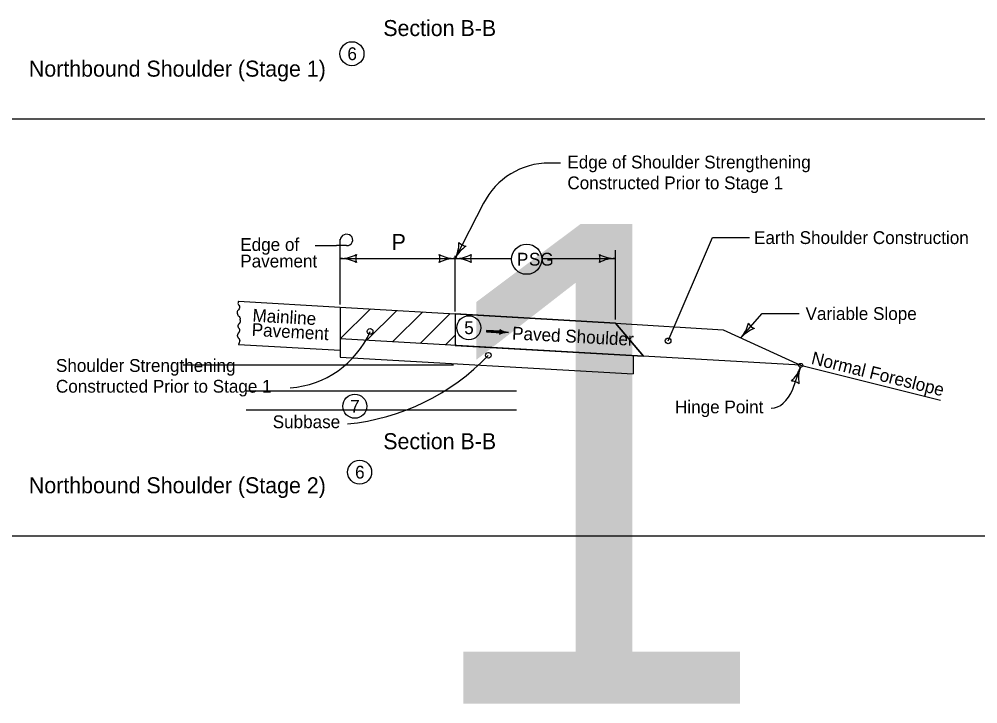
# Model space of a CAD drawing. Extents: x 10133 to 81668, y 7924 to 12229.
# Drawn here: x 11002 to 12201, y 10409 to 11265 of the extents above; entities that cross this region are included whole.
import ezdxf

# ---------------------------------------------------------------- set-up
doc = ezdxf.new("R2010")
doc.units = 0
for name, color, linetype in [('Cell', 7, 'Continuous'), ('dsnTextFinalPlan', 7, 'Continuous'), ('Level 1', 7, 'Continuous'), ('Level 12', 7, 'Continuous'), ('Level 4', 7, 'Continuous'), ('SheetText', 7, 'Continuous')]:
    doc.layers.add(name, color=color, linetype=linetype)

msp = doc.modelspace()

# ---------------------------------------------------------------- linework, layer by layer
at = {"layer": 'Cell'}
for p, q in [((11747.9, 10885.3), (11547.4, 10896.9)), ((11547.4, 10896.9), (11547.4, 10857.1)), ((11783, 10843.8), (11747.9, 10885.3)), ((11547.4, 10857.1), (11783, 10843.8))]:
    msp.add_line(p, q, dxfattribs=at)
at = {"layer": 'dsnTextFinalPlan'}
for p, q in [((11276.2, 10912.7), (11403.6, 10905.3)), ((11403.6, 10905.3), (11403.6, 10851.3)), ((11403.6, 10905.3), (11747.9, 10885.2)), ((11547.4, 10896.9), (11547.4, 10857.1)), ((11747.5, 10885.4), (11747.5, 10885.4)), ((11747.9, 10885.3), (11882.7, 10876.9)), ((11747.9, 10885.2), (11783, 10843.8)), ((11882.7, 10876.9), (11979.7, 10832.5)), ((11276.2, 10858.7), (11403.6, 10851.3)), ((11979.7, 10832.5), (11403.6, 10865.7)), ((11770.2, 10858.9), (11770.2, 10858.9)), ((11403.6, 10851.3), (11403.6, 10842.8)), ((11403.6, 10842.8), (11770.2, 10821.7)), ((11770.2, 10844.5), (11770.2, 10821.7)), ((11206.9, 10833.3), (11545.4, 10833.3)), ((11979.7, 10832.5), (12154.7, 10789.1)), ((11285.6, 10800.4), (11624.1, 10800.4)), ((11285.6, 10776.7), (11624.1, 10776.7))]:
    msp.add_line(p, q, dxfattribs=at)
msp.add_ellipse((11979.7, 10832.5), major_axis=(2.58, 0), ratio=0.913811, dxfattribs=at)
for points in [[(11276.2, 10912.7), (11275.7, 10909.1), (11276.7, 10907.6), (11277.6, 10905.3), (11277, 10903.2), (11275.1, 10900.8), (11274.5, 10898.9), (11275.1, 10896.6), (11275.9, 10894.3), (11277, 10893.6), (11278.3, 10891), (11278.3, 10890.2)], [(11276.4, 10873.1), (11276.6, 10873.3), (11276.8, 10873.6), (11277.1, 10874.1), (11277.4, 10874.7), (11277.5, 10875), (11277.6, 10875.4), (11277.8, 10876), (11277.8, 10876.6), (11277.8, 10877.2), (11277.7, 10877.5), (11277.7, 10877.6), (11277.6, 10877.7), (11277.4, 10878.1), (11277.1, 10878.5), (11276.8, 10878.8), (11276.6, 10879.2), (11276.4, 10879.5), (11276.3, 10879.8), (11276, 10880.4), (11275.8, 10880.9), (11275.8, 10881.2), (11275.7, 10881.5), (11275.7, 10881.6), (11275.7, 10881.8), (11275.9, 10882.6), (11276.1, 10883.1), (11276.3, 10883.6), (11276.8, 10884.2), (11277.3, 10884.8), (11277.8, 10885.3), (11278, 10885.6), (11278.2, 10886), (11278.4, 10886.4), (11278.6, 10886.9), (11278.7, 10887.4), (11278.7, 10887.6), (11278.7, 10887.7), (11278.8, 10887.9), (11278.7, 10888.4), (11278.6, 10888.9), (11278.5, 10889), (11278.4, 10889.1), (11278.4, 10889.3), (11278.4, 10889.4), (11278.3, 10890.2)], [(11276.4, 10873.1), (11276.2, 10872.8), (11275.9, 10872.6), (11275.7, 10872.4), (11275.5, 10872.1), (11275.4, 10871.8), (11275.2, 10871.5), (11275, 10870.9), (11274.8, 10870.7), (11274.8, 10870.4), (11274.7, 10870.1), (11274.7, 10869.9), (11274.6, 10869.8), (11274.6, 10869.3), (11274.8, 10868.8), (11275, 10868.2), (11275.2, 10867.7), (11275.7, 10867.1), (11276.2, 10866.6), (11276.7, 10866), (11276.9, 10865.7), (11277.1, 10865.4), (11277.5, 10864.4), (11277.7, 10863.9), (11277.7, 10863.5), (11277.6, 10863.2), (11277.6, 10862.9), (11277.5, 10862.6), (11277.5, 10862.3), (11277.1, 10861.2), (11277, 10860.6), (11276.8, 10860), (11276.5, 10859.4), (11276.4, 10859.1), (11276.3, 10858.8), (11276.2, 10858.7)]]:
    msp.add_spline(points, degree=3, dxfattribs=at)
at = {"layer": 'Level 1'}
msp.add_line((10147.1, 10619.2), (13242.8, 10619.2), dxfattribs=at)
at = {"layer": 'Level 12'}
for centre in [(11418.2, 11222.2), (11564.4, 10879.5), (11421.7, 10781.3), (11427.8, 10698.9)]:
    msp.add_circle(centre, 15, dxfattribs=at)
at = {"layer": 'Level 4'}
msp.add_line((12302.7, 11140.2), (10147.1, 11140.2), dxfattribs=at)
for centre in [(11440.9, 10874.9), (11440.9, 10874.9), (11813.9, 10863.1), (11813.9, 10863.1), (11588.9, 10845), (11588.9, 10845)]:
    msp.add_circle(centre, 3.54, dxfattribs=at)
at = {"layer": 'SheetText'}
for p, q in [((11665.1, 11085.6), (11679.4, 11085.6)), ((11582.7, 11035.2), (11547.4, 10966)), ((11403.6, 10969.3), (11403.6, 10990.2)), ((11813.9, 10863.1), (11869.6, 10992.2)), ((11869.6, 10992.2), (11915.9, 10992.2)), ((11372.3, 10982.2), (11398.9, 10982.2)), ((11411.4, 10982.2), (11398.9, 10982.2)), ((11403.6, 10908.4), (11403.6, 10969.3)), ((11547.4, 10899.8), (11547.4, 10969.3)), ((11655.8, 10966.2), (11747.9, 10966.2)), ((11747.9, 10889.9), (11747.9, 10976.5)), ((11403.6, 10966), (11618, 10966)), ((11403.6, 10865.7), (11441.4, 10903.1)), ((11436.7, 10863.8), (11474.5, 10901.2)), ((11468.9, 10861.9), (11506.7, 10899.3)), ((11503.5, 10859.9), (11541.3, 10897.3)), ((11904.9, 10866.8), (11931.5, 10897.2)), ((11931.5, 10897.2), (11977.8, 10897.2)), ((11535.1, 10858.1), (11547.4, 10870.2)), ((11604.7, 10874.2), (11586.5, 10875.2)), ((11604.6, 10873.2), (11604.6, 10873.2)), ((11604.7, 10875.2), (11604.7, 10875.2)), ((11970, 10802.5), (11979.4, 10830.1))]:
    msp.add_line(p, q, dxfattribs=at)
for points in [[(11604.7, 10875.1), (11586.5, 10876.2), (11586.4, 10874.3), (11604.6, 10873.2), (11604.6, 10874.8), (11586.7, 10875.9), (11586.7, 10874.4), (11604.2, 10873.5), (11604.3, 10874.6), (11587, 10875.7), (11586.9, 10874.7), (11604, 10873.7), (11604.1, 10874.4), (11587.2, 10875.4), (11587.1, 10874.9), (11603.7, 10873.9)], [(11604.3, 10876.4), (11605, 10875.2), (11605, 10873.5), (11604.2, 10872.1), (11606.9, 10873), (11610.1, 10873.7), (11611, 10873.8), (11608.8, 10874.3), (11605.6, 10875.6), (11604.6, 10876.1), (11604.7, 10872.6), (11609.7, 10873.8), (11605.1, 10875.4), (11605.1, 10873), (11608.5, 10873.9), (11605.5, 10874.8), (11605.2, 10873.4), (11607.4, 10873.9), (11605.8, 10874.4), (11605.7, 10873.7), (11606.5, 10873.9)]]:
    msp.add_lwpolyline(points, dxfattribs=at)
msp.add_circle((11636.9, 10965.2), 18.9, dxfattribs=at)
for centre, radius, start, end in [((11665.1, 10993.1), 92.4, 90, 152.9341), ((11509.5, 10985.3), 42.5, 332.9341, 1.0066), ((11585.2, 10946.7), 42.5, 124.8616, 152.9341), ((11563.6, 10997.7), 16.4, 225.2008, 260.6675), ((11403.6, 11008.5), 42.5, 270, 298.0725), ((11439.3, 10966), 16.4, 162.2666, 197.7334), ((11511.8, 10966), 16.4, 342.2666, 17.7334), ((11547.4, 11008.5), 42.5, 241.9275, 270), ((11547.4, 11008.5), 42.5, 270, 298.0725), ((11583, 10966), 16.4, 162.2666, 197.7334), ((11712.3, 10966.2), 16.4, 342.2666, 17.7333), ((11747.9, 11008.7), 42.5, 241.9275, 270), ((11747.9, 10923.7), 42.5, 90, 118.0725), ((11403.6, 10923.5), 42.5, 61.9275, 90), ((11547.4, 10923.5), 42.5, 90, 118.0725), ((11547.4, 10923.5), 42.5, 61.9275, 90), ((11872.9, 10894.7), 42.5, 318.8454, 346.9178), ((11928.3, 10893.6), 16.4, 211.112, 246.5787), ((11332.4, 10923), 118.9, 274.0851, 336.0699), ((11936.9, 10838.8), 42.5, 110.7729, 138.8454), ((11384.9, 11039.8), 282, 275.6784, 316.2844), ((11939.2, 10843.9), 42.5, 312.9788, 341.0513), ((12019.6, 10816.3), 42.5, 161.0513, 189.1238), ((11967.9, 10796.4), 16.4, 53.3179, 88.7846)]:
    msp.add_arc(centre, radius, start, end, dxfattribs=at)
for centre, major_axis, ratio, start_param, end_param in [((11411.4, 10989.3), (-7.81, 0), 0.913811, 1.570796, 6.283185), ((11600.9, 10874.4), (3.88, 0), 0.913811, 5.202895, 7.237436), ((11613.2, 10853.4), (22.2, 0), 0.913811, 1.537172, 2.061295), ((11615.9, 10893.8), (-22.2, 0), 0.913811, 0.954258, 1.478381), ((11942.9, 10840.4), (0, 61.5), 0.559383, 3.141593, 4.048985)]:
    msp.add_ellipse(centre, major_axis=major_axis, ratio=ratio, start_param=start_param, end_param=end_param, dxfattribs=at)

# ---------------------------------------------------------------- texts
at = {"layer": 'Level 12'}
for s, p in [('6', (11412.5, 11214.2)), ('5', (11558.7, 10871.5)), ('7', (11416, 10773.3)), ('6', (11422.1, 10690.9))]:
    msp.add_text(s, height=16, dxfattribs=at).set_placement(p)
at = {"layer": 'SheetText'}
for s, height, p in [('Section B-B', 20, (11457.4, 11244.3)), ('Northbound Shoulder (Stage 1)', 20, (11013.8, 11193.5)), ('Edge of Shoulder Strengthening', 16, (11687.8, 11078.7)), ('Constructed Prior to Stage 1', 16, (11687.8, 11052.7)), ('1', 600, (11496.6, 10409.2)), ('Edge of ', 16, (11278.4, 10975.6)), ('P', 20, (11467.8, 10976.7)), ('Earth Shoulder Construction', 16, (11921.4, 10984.2)), ('Pavement', 16, (11278.4, 10954.9)), ('P', 16, (11624.7, 10957.2)), ('SG', 16, (11639.7, 10957.2)), ('Variable Slope', 16, (11985.9, 10889.2)), ('Shoulder Strengthening', 16, (11047.7, 10824.3)), ('Constructed Prior to Stage 1', 16, (11047.7, 10798.3)), ('Hinge Point', 16, (11822.5, 10772.5)), ('Subbase', 16, (11319, 10753.9)), ('Section B-B', 20, (11457.4, 10727.6)), ('Northbound Shoulder (Stage 2)', 20, (11013.8, 10672.5))]:
    msp.add_text(s, height=height, dxfattribs=at).set_placement(p)
for s, rotation, p in [('Mainline', 356.7346, (11293.4, 10887.3)), ('Pavement', 356.7346, (11292.4, 10869.4)), ('Paved Shoulder ', 356.983, (11618.3, 10864.9)), ('Normal Foreslope', 346.0988, (11992, 10834.5))]:
    msp.add_text(s, height=16, rotation=rotation, dxfattribs=at).set_placement(p)

doc.saveas('drawing.dxf')
